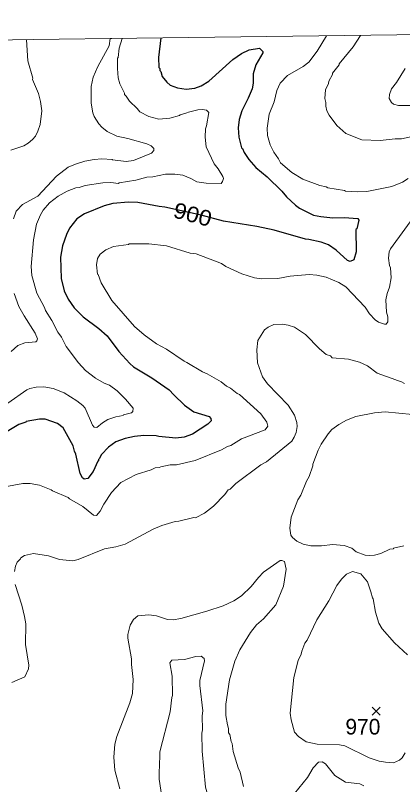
# Model space of a CAD drawing. Extents: x 265.7 to 292.1, y 7676.2 to 7704.2.
# Drawn here: x 276.788 to 278.768, y 7700.203 to 7704.136 of the extents above; entities that cross this region are included whole.
import ezdxf
from ezdxf.enums import TextEntityAlignment as Align

# ---------------------------------------------------------------- set-up
doc = ezdxf.new("R2010")
doc.units = 0
doc.header["$LTSCALE"] = 0.032
for name, color, linetype, lineweight in [('1', 7, 'Continuous', 25), ('2', 7, 'Continuous', 13), ('21', 7, 'Continuous', 25), ('63', 7, 'Continuous', 25)]:
    doc.layers.add(name, color=color, linetype=linetype, lineweight=lineweight)
doc.layers.add('61', color=7, linetype='Continuous')

msp = doc.modelspace()

# ---------------------------------------------------------------- linework, layer by layer
at = {"layer": '1'}
for points in [[(277.5319, 7704.0209), (277.5199, 7703.9214), (277.5215, 7703.8695), (277.5263, 7703.864), (277.5263, 7703.8552), (277.5311, 7703.8496), (277.5391, 7703.8241), (277.5622, 7703.7945), (277.5798, 7703.7802), (277.6173, 7703.7658), (277.6604, 7703.7594), (277.7051, 7703.7642), (277.737, 7703.7762), (277.7769, 7703.8001), (277.899, 7703.9102), (277.9444, 7703.9414), (277.9827, 7703.9597), (278.0362, 7703.9685), (278.0538, 7703.9525), (278.0538, 7703.9446), (278.0178, 7703.8831), (278.0043, 7703.8368), (278.0035, 7703.7905), (277.9987, 7703.7602), (277.9787, 7703.7123), (277.9452, 7703.6485), (277.9317, 7703.6038), (277.9269, 7703.5607), (277.9301, 7703.5145), (277.9444, 7703.4586), (277.9492, 7703.4554), (277.958, 7703.4347), (277.9811, 7703.3995), (278.0178, 7703.358), (278.0745, 7703.3102), (278.1495, 7703.2375), (278.1742, 7703.208), (278.2197, 7703.1657), (278.2405, 7703.1514), (278.3115, 7703.1147), (278.3498, 7703.1075), (278.4105, 7703.1019), (278.4695, 7703.1035), (278.5389, 7703.0971), (278.5445, 7703.0891), (278.5333, 7703.0445), (278.5285, 7703.0413), (278.5301, 7702.9272), (278.5174, 7702.8857), (278.499, 7702.8777), (278.4855, 7702.8833), (278.4272, 7702.9367), (278.3889, 7702.9623), (278.3514, 7702.9774), (278.2876, 7702.991), (278.2716, 7702.9918), (278.1104, 7703.0381), (278.0226, 7703.0572), (277.8519, 7703.0843), (277.7374, 7703.114), (277.5518, 7703.1562), (277.5231, 7703.1585), (277.4146, 7703.1801), (277.3667, 7703.1809), (277.2869, 7703.1737), (277.2422, 7703.1625), (277.1417, 7703.1218), (277.1018, 7703.0955), (277.0651, 7703.0492), (277.0491, 7703.0165), (277.0284, 7702.9575), (277.018, 7702.9), (277.022, 7702.7915), (277.0371, 7702.7277), (277.0571, 7702.6846), (277.089, 7702.6415), (277.1353, 7702.5952), (277.2151, 7702.5353), (277.2574, 7702.497), (277.3172, 7702.4173), (277.3731, 7702.3566), (277.3922, 7702.3398), (277.4864, 7702.2824), (277.5742, 7702.2209), (277.5973, 7702.1954), (277.6532, 7702.1435), (277.6995, 7702.11), (277.7785, 7702.0853), (277.7872, 7702.0749), (277.7888, 7702.063), (277.7713, 7702.0454), (277.6931, 7701.9951), (277.6508, 7701.98), (277.6077, 7701.9744), (277.5215, 7701.9824)], [(277.2638, 7701.9281), (277.2287, 7701.8906), (277.2167, 7701.8683), (277.2127, 7701.8659), (277.2127, 7701.8579), (277.2095, 7701.8563), (277.1864, 7701.8036), (277.1577, 7701.7677), (277.1401, 7701.7653), (277.1313, 7701.7725), (277.1193, 7701.7932), (277.0978, 7701.893), (277.0906, 7701.9074), (277.0834, 7701.9361), (277.0332, 7702.0271), (277.0028, 7702.0494), (276.9406, 7702.0709), (276.9119, 7702.0725), (276.8433, 7702.0605), (276.8409, 7702.0566), (276.805, 7702.0446), (276.7299, 7701.9983)], [(277.5215, 7701.9824), (277.5072, 7701.9863), (277.4449, 7701.9887), (277.397, 7701.9839), (277.3492, 7701.972), (277.3013, 7701.9552), (277.2638, 7701.9281)]]:
    msp.add_lwpolyline(points, dxfattribs=at)
at = {"layer": '2'}
for points in [[(278.3784, 7704.0321), (278.33, 7703.9536), (278.2881, 7703.8978), (278.2584, 7703.8751), (278.179, 7703.8288), (278.1423, 7703.7905), (278.124, 7703.7522), (278.1104, 7703.6948), (278.0857, 7703.631), (278.0745, 7703.5591), (278.0769, 7703.5224), (278.0897, 7703.4746), (278.1088, 7703.4378), (278.1328, 7703.4035), (278.1439, 7703.382), (278.2014, 7703.3325), (278.2572, 7703.2982), (278.345, 7703.2663), (278.3769, 7703.2599), (278.3849, 7703.2551), (278.4711, 7703.2407), (278.4751, 7703.2368), (278.5365, 7703.2336), (278.5844, 7703.236), (278.7121, 7703.2615), (278.7663, 7703.2838), (278.7959, 7703.3022)], [(278.5522, 7704.0343), (278.515, 7703.9749), (278.444, 7703.8887), (278.4432, 7703.8831), (278.4097, 7703.8416), (278.4089, 7703.8344), (278.3905, 7703.8001), (278.3881, 7703.7874), (278.3737, 7703.7554), (278.3698, 7703.7108), (278.3745, 7703.6916), (278.3745, 7703.6724), (278.3809, 7703.6485), (278.3913, 7703.6262), (278.4312, 7703.5727), (278.4767, 7703.5328), (278.5589, 7703.4993), (278.653, 7703.4969), (278.7296, 7703.5057), (278.7616, 7703.5057), (278.9012, 7703.536)], [(276.7651, 7703.4466), (276.8305, 7703.4698), (276.8536, 7703.4825), (276.876, 7703.5017), (276.8903, 7703.5192), (276.9031, 7703.544), (276.9151, 7703.5783), (276.923, 7703.6485), (276.9167, 7703.6964), (276.9071, 7703.7363), (276.876, 7703.8081), (276.8768, 7703.8161), (276.8512, 7703.9039), (276.8454, 7704.0119)], [(277.484, 7703.4315), (277.4952, 7703.4458), (277.496, 7703.4554), (277.4824, 7703.469), (277.4593, 7703.4801), (277.3635, 7703.5065), (277.3061, 7703.5184), (277.2566, 7703.5424), (277.2295, 7703.5647), (277.2151, 7703.5815), (277.1912, 7703.6198), (277.184, 7703.6389), (277.1752, 7703.6868), (277.176, 7703.773), (277.1856, 7703.8209), (277.2095, 7703.8751), (277.267, 7703.9805), (277.2734, 7704.0175), (277.2813, 7704.0176)], [(277.4242, 7703.6429), (277.4098, 7703.6605), (277.3707, 7703.6972), (277.3547, 7703.7235), (277.3452, 7703.7323), (277.3452, 7703.7395), (277.3228, 7703.7858), (277.314, 7703.8177), (277.3101, 7703.8656), (277.3101, 7703.9174), (277.3133, 7703.9214), (277.318, 7703.9693), (277.3333, 7704.0183)], [(278.7799, 7703.8648), (278.736, 7703.7937), (278.7113, 7703.7602), (278.7009, 7703.7315), (278.6985, 7703.7115), (278.7105, 7703.6916), (278.7201, 7703.6828), (278.7472, 7703.6748), (278.807, 7703.6764)], [(276.7491, 7702.1531), (276.8464, 7702.2217), (276.8624, 7702.2281), (276.8943, 7702.2345), (276.9342, 7702.2377), (276.9821, 7702.2281), (277.038, 7702.2066), (277.1018, 7702.1659), (277.1337, 7702.1412), (277.1449, 7702.1276), (277.1816, 7702.0414), (277.1904, 7702.031), (277.2039, 7702.0294), (277.2327, 7702.0534), (277.2614, 7702.0693), (277.3013, 7702.0837), (277.3396, 7702.0901), (277.3412, 7702.0933), (277.3811, 7702.1036), (277.3891, 7702.1116), (277.3899, 7702.1276), (277.3515, 7702.1739), (277.3085, 7702.217), (277.2686, 7702.2449), (277.2422, 7702.2561), (277.1983, 7702.2816), (277.1465, 7702.3207), (277.1114, 7702.3598), (277.0483, 7702.4436), (277.0236, 7702.4907), (277.0044, 7702.517), (276.9741, 7702.576), (276.9414, 7702.6271), (276.9374, 7702.6431), (276.8983, 7702.7165), (276.8728, 7702.8059), (276.8688, 7702.8521), (276.88, 7702.9894), (276.8967, 7703.0692), (276.9167, 7703.1171), (276.9302, 7703.141), (276.9629, 7703.1785), (277.0076, 7703.2128), (277.0523, 7703.2376), (277.097, 7703.2551), (277.1146, 7703.2567), (277.1449, 7703.2671), (277.2359, 7703.2798), (277.2758, 7703.2814), (277.3149, 7703.2767), (277.3188, 7703.2806), (277.4034, 7703.2934), (277.4601, 7703.3094), (277.4912, 7703.311), (277.555, 7703.3237), (277.6029, 7703.3237), (277.6444, 7703.3189), (277.6843, 7703.303), (277.7162, 7703.2854), (277.7641, 7703.279), (277.8399, 7703.2767), (277.8471, 7703.2878), (277.8511, 7703.303), (277.8487, 7703.3118), (277.8247, 7703.3517), (277.804, 7703.3772), (277.7625, 7703.465), (277.7585, 7703.5129), (277.7601, 7703.5559), (277.7657, 7703.5719), (277.7769, 7703.6397), (277.7657, 7703.6517), (277.745, 7703.6549), (277.721, 7703.6541), (277.6731, 7703.6421), (277.6652, 7703.6373)], [(277.6652, 7703.6373), (277.63, 7703.6286), (277.6269, 7703.6238), (277.5774, 7703.6102), (277.5215, 7703.6062), (277.4705, 7703.619), (277.4242, 7703.6429)], [(277.1912, 7703.4003), (277.2295, 7703.4027), (277.2829, 7703.4003), (277.2837, 7703.3979), (277.354, 7703.3884), (277.3923, 7703.3947), (277.484, 7703.4315)], [(276.7786, 7703.0963), (276.7922, 7703.1354), (276.8249, 7703.1697), (276.9031, 7703.2128), (276.9981, 7703.315), (277.0587, 7703.3596), (277.0962, 7703.3756), (277.1433, 7703.3908), (277.1912, 7703.4003)], [(278.8382, 7703.1258), (278.7057, 7702.9431), (278.6993, 7702.9272), (278.6961, 7702.8952), (278.7009, 7702.8569), (278.7057, 7702.845), (278.7097, 7702.7947), (278.7009, 7702.7468), (278.6889, 7702.7149), (278.6818, 7702.6814), (278.6849, 7702.6191), (278.6913, 7702.5952), (278.6913, 7702.5697), (278.6842, 7702.5577), (278.6754, 7702.5569), (278.6435, 7702.5673), (278.6275, 7702.5792), (278.5988, 7702.6096), (278.5764, 7702.6447), (278.4767, 7702.7484), (278.4408, 7702.7699), (278.3769, 7702.7971), (278.3291, 7702.8075), (278.2892, 7702.8106), (278.1934, 7702.8035), (278.1296, 7702.7907), (278.0466, 7702.7891), (278.0099, 7702.7939), (277.946, 7702.8146), (277.8646, 7702.8521), (277.8415, 7702.8673), (277.713, 7702.9168), (277.6811, 7702.9208), (277.5614, 7702.9575), (277.4705, 7702.9678), (277.3699, 7702.9678), (277.3659, 7702.9647), (277.2901, 7702.9543), (277.2502, 7702.9375), (277.2215, 7702.916), (277.2087, 7702.8936), (277.2031, 7702.8617), (277.2087, 7702.8138), (277.2119, 7702.8122), (277.2263, 7702.7692), (277.2805, 7702.679), (277.397, 7702.5457), (277.4457, 7702.5026), (277.5103, 7702.4564), (277.5598, 7702.4292), (277.6508, 7702.3678)], [(276.7658, 7702.4181), (276.8002, 7702.4484), (276.8369, 7702.4627), (276.8927, 7702.4667), (276.8983, 7702.4715), (276.9007, 7702.4819), (276.8895, 7702.5106), (276.8329, 7702.6), (276.8065, 7702.6479), (276.7818, 7702.7149)], [(278.4073, 7702.3861), (278.3993, 7702.3949), (278.3769, 7702.4029), (278.3434, 7702.4308), (278.2716, 7702.505), (278.2142, 7702.5417), (278.1822, 7702.5529), (278.1535, 7702.5577), (278.1088, 7702.5561), (278.0801, 7702.5425), (278.0609, 7702.529), (278.0274, 7702.4739), (278.0218, 7702.426), (278.0258, 7702.359), (278.0514, 7702.288), (278.0769, 7702.2529), (278.1822, 7702.1436), (278.2149, 7702.0925), (278.2269, 7702.0542), (278.2285, 7702.035), (278.2237, 7702.0039), (278.2134, 7701.9792), (278.2014, 7701.96), (278.0721, 7701.8531), (278.0434, 7701.8387), (277.9157, 7701.743), (277.8854, 7701.7142), (277.8758, 7701.7103), (277.8583, 7701.6871), (277.8016, 7701.6273), (277.7553, 7701.5906), (277.709, 7701.5674), (277.7003, 7701.5682), (277.6237, 7701.5499), (277.6045, 7701.5491), (277.5375, 7701.5283), (277.4928, 7701.5092), (277.3492, 7701.4326), (277.3013, 7701.419), (277.2438, 7701.4086), (277.1098, 7701.3536), (277.0811, 7701.348), (277.014, 7701.3544), (276.9566, 7701.3735), (276.88, 7701.3855), (276.8353, 7701.3743), (276.8153, 7701.3631), (276.8137, 7701.3576), (276.7978, 7701.3408), (276.789, 7701.3193), (276.7842, 7701.2929)], [(278.7336, 7702.2736), (278.6371, 7702.3071), (278.5884, 7702.3446), (278.5477, 7702.363), (278.4903, 7702.3789), (278.4073, 7702.3861)], [(277.6508, 7702.3678), (277.6652, 7702.3622), (277.745, 7702.3143), (277.7689, 7702.3039), (277.8407, 7702.2632), (277.867, 7702.2401)], [(278.7775, 7702.2545), (278.7584, 7702.264), (278.7392, 7702.2688), (278.7336, 7702.2736)], [(277.867, 7702.2401), (277.887, 7702.2297), (277.9213, 7702.2026), (277.9341, 7702.197), (278.0426, 7702.0989), (278.0737, 7702.0558), (278.0793, 7702.0358), (278.0649, 7702.0167), (277.9444, 7701.9704), (277.8886, 7701.9377), (277.8726, 7701.9321), (277.8415, 7701.9145), (277.7067, 7701.8595), (277.6109, 7701.8379), (277.579, 7701.8379), (277.5311, 7701.8284), (277.5231, 7701.8244), (277.5032, 7701.8228), (277.4816, 7701.8124), (277.405, 7701.7885), (277.3268, 7701.7485), (277.2789, 7701.6959), (277.2398, 7701.6368), (277.2207, 7701.6009), (277.2023, 7701.5794), (277.188, 7701.5802), (277.1321, 7701.6257), (277.0651, 7701.664), (277.0587, 7701.6704), (276.9773, 7701.7047), (276.9709, 7701.7103), (276.9119, 7701.7334), (276.864, 7701.7422), (276.8257, 7701.743), (276.7347, 7701.7262)], [(278.8174, 7702.0949), (278.6786, 7702.1084), (278.6243, 7702.1044), (278.5286, 7702.0853), (278.4807, 7702.0669), (278.4416, 7702.0446), (278.4065, 7702.0191), (278.3873, 7701.9967), (278.3506, 7701.9433), (278.3362, 7701.9137), (278.3091, 7701.8419), (278.3091, 7701.8339), (278.2892, 7701.7781), (278.2764, 7701.7541), (278.2477, 7701.6823), (278.2325, 7701.6584), (278.1982, 7701.5706), (278.191, 7701.5148), (278.1966, 7701.4789), (278.2046, 7701.4669), (278.2269, 7701.4477), (278.2588, 7701.4318), (278.2987, 7701.4246), (278.353, 7701.4238), (278.4089, 7701.4302), (278.4695, 7701.4262), (278.5078, 7701.4126), (278.5309, 7701.3927), (278.5764, 7701.3767), (278.6004, 7701.3743), (278.6243, 7701.3767), (278.6562, 7701.3855), (278.7025, 7701.4062), (278.7201, 7701.4086), (278.7209, 7701.4118), (278.7743, 7701.4246)], [(277.3212, 7700.1806), (277.2965, 7700.2763), (277.2909, 7700.3434), (277.2965, 7700.4104), (277.3069, 7700.4487), (277.3739, 7700.621), (277.3867, 7700.6689), (277.3899, 7700.7407), (277.3819, 7700.8173), (277.3819, 7700.8461), (277.3627, 7700.9514), (277.3627, 7700.9706), (277.3755, 7701.0184), (277.3914, 7701.0472), (277.4146, 7701.0655), (277.4705, 7701.0719), (277.5088, 7701.0663), (277.5662, 7701.0472), (277.5949, 7701.0456), (277.6332, 7701.0527), (277.7673, 7701.0894), (277.8503, 7701.1174), (277.9045, 7701.1421), (277.9444, 7701.1676), (277.9931, 7701.2155), (278.0306, 7701.2618), (278.057, 7701.2889), (278.1423, 7701.3488), (278.1503, 7701.3488), (278.1639, 7701.3432), (278.1727, 7701.3041), (278.1583, 7701.2179), (278.12, 7701.1222), (278.0562, 7701.0511), (278.021, 7701.0192), (277.9899, 7700.9809), (277.9349, 7700.8924), (277.9093, 7700.8349), (277.8822, 7700.7391), (277.8646, 7700.6147), (277.8646, 7700.5572), (277.8718, 7700.5093), (277.8782, 7700.4902), (277.8774, 7700.4678), (277.8838, 7700.4591), (277.8918, 7700.4231), (277.8966, 7700.4136), (277.9006, 7700.3729), (277.9261, 7700.2891), (277.9365, 7700.2659), (277.9548, 7700.1933)], [(278.7919, 7700.8668), (278.7264, 7700.9275), (278.6626, 7700.9993), (278.6466, 7701.028), (278.6283, 7701.0855), (278.6171, 7701.1525), (278.6131, 7701.1581), (278.6059, 7701.1892), (278.5876, 7701.2403), (278.5533, 7701.281), (278.511, 7701.2929), (278.4815, 7701.2786), (278.4543, 7701.253), (278.4312, 7701.2211), (278.3897, 7701.1429), (278.3295, 7701.0457), (278.2796, 7700.9418), (278.2684, 7700.9259), (278.2517, 7700.886), (278.2485, 7700.87), (278.2341, 7700.8381), (278.2118, 7700.7503), (278.1926, 7700.5684), (278.1982, 7700.5349), (278.2157, 7700.471), (278.2357, 7700.4487), (278.2748, 7700.4223), (278.3307, 7700.4096), (278.4456, 7700.4064), (278.4727, 7700.4008), (278.5972, 7700.3394), (278.6482, 7700.3234), (278.6802, 7700.317), (278.7201, 7700.3146), (278.752, 7700.3282), (278.7655, 7700.3394), (278.7807, 7700.3657)], [(276.7874, 7701.2259), (276.8209, 7701.1206), (276.8353, 7701.0631), (276.8409, 7701.0248), (276.8401, 7700.9195), (276.8576, 7700.8142), (276.8552, 7700.795), (276.8361, 7700.7543), (276.7698, 7700.7256)], [(277.5439, 7700.096), (277.5231, 7700.2316), (277.5223, 7700.2827), (277.5247, 7700.2859), (277.5271, 7700.3705), (277.579, 7700.5748), (277.5877, 7700.6482), (277.5917, 7700.6585), (277.5893, 7700.7583), (277.5782, 7700.8253), (277.5878, 7700.8389), (277.6524, 7700.8421), (277.7098, 7700.858), (277.7378, 7700.8596), (277.7529, 7700.8477), (277.7545, 7700.8357), (277.7314, 7700.7359), (277.7314, 7700.7104), (277.7457, 7700.5795), (277.7434, 7700.554), (277.745, 7700.4838)], [(277.745, 7700.4838), (277.7418, 7700.4662), (277.7426, 7700.3737), (277.7601, 7700.1901), (277.7729, 7700.1423), (277.792, 7700.0968), (277.796, 7700.096)], [(278.2157, 7700.1582), (278.282, 7700.2396), (278.3107, 7700.2891), (278.3378, 7700.317), (278.357, 7700.3194), (278.3737, 7700.309), (278.4208, 7700.2492), (278.4751, 7700.2149), (278.5493, 7700.2069), (278.5685, 7700.1973)]]:
    msp.add_lwpolyline(points, dxfattribs=at)
at = {"layer": '21'}
for p, q in [((278.6115, 7700.5992), (278.6527, 7700.558)), ((278.6527, 7700.5992), (278.6115, 7700.558))]:
    msp.add_line(p, q, dxfattribs=at)
at = {"layer": '63', "lineweight": 13}
msp.add_lwpolyline([(276.3468, 7704.0052), (276.8782, 7704.0123), (277.4097, 7704.0193), (277.9411, 7704.0263), (278.4725, 7704.0333), (279.0039, 7704.0403), (279.5354, 7704.0473), (280.0668, 7704.0543), (280.5982, 7704.0612), (281.1296, 7704.0681), (281.661, 7704.075), (282.1925, 7704.0819), (282.7239, 7704.0888), (283.2553, 7704.0956), (283.7867, 7704.1025), (284.3181, 7704.1093), (284.8495, 7704.1161), (285.3809, 7704.1229), (285.9123, 7704.1296), (286.4437, 7704.1364)], dxfattribs=at)

# ---------------------------------------------------------------- texts
at = {"layer": '61', "width": 1.1}
msp.add_text('900', height=0.08, rotation=345.175, dxfattribs=at).set_placement((277.6844, 7703.0797), align=Align.CENTER)
at = {"layer": '61'}
msp.add_text('970', height=0.08, dxfattribs=at).set_placement((278.5645, 7700.4591), align=Align.CENTER)

doc.saveas('drawing.dxf')
